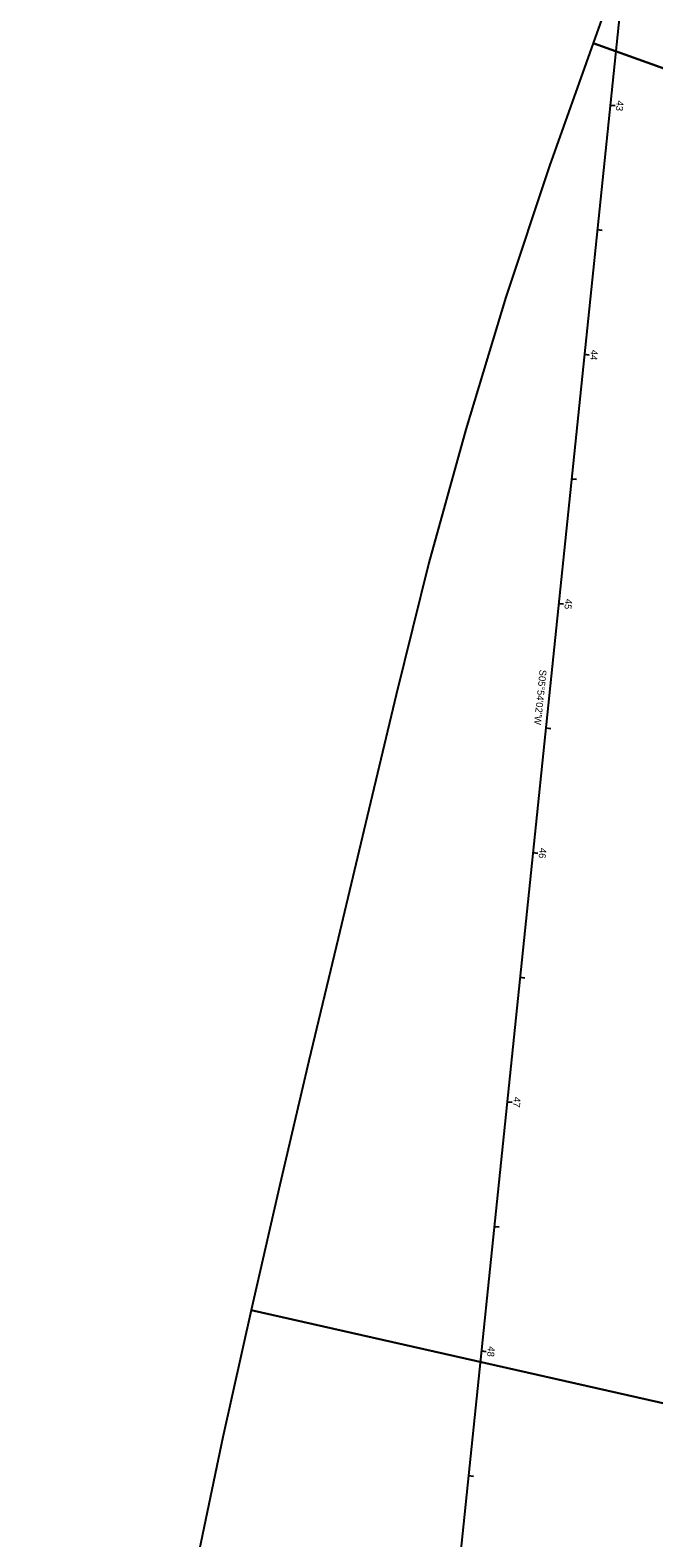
# Model space of a CAD drawing. Extents: x 172043 to 172847, y 249504 to 259737.
# Drawn here: x 172096 to 172345, y 254873 to 255475 of the extents above; entities that cross this region are included whole.
import ezdxf

# ---------------------------------------------------------------- set-up
doc = ezdxf.new("R2010")
doc.units = 0
for name, color, linetype in [('PM_X_Surveyed_Line', 7, 'Continuous'), ('PV_X_Shoulder', 7, 'Continuous'), ('RW_X_CL_100_Distances', 7, 'Continuous')]:
    doc.layers.add(name, color=color, linetype=linetype)

msp = doc.modelspace()

# ---------------------------------------------------------------- linework, layer by layer
at = {"layer": 'PM_X_Surveyed_Line'}
for p, q in [((172428.67, 256423.35), (172177.28, 253990.91)), ((172409.1, 256234.03), (172171.47, 253934.66)), ((172327.53, 255444.75), (172329.52, 255444.55)), ((172327.53, 255444.75), (172329.52, 255444.55)), ((172322.39, 255395.02), (172324.38, 255394.81)), ((172317.25, 255345.28), (172319.24, 255345.08)), ((172317.25, 255345.28), (172319.24, 255345.08)), ((172312.11, 255295.55), (172314.1, 255295.34)), ((172306.97, 255245.81), (172308.96, 255245.61)), ((172306.97, 255245.81), (172308.96, 255245.61)), ((172301.83, 255196.08), (172303.82, 255195.87)), ((172296.69, 255146.34), (172298.68, 255146.14)), ((172296.69, 255146.34), (172298.68, 255146.14)), ((172291.55, 255096.61), (172293.54, 255096.4)), ((172286.41, 255046.87), (172288.4, 255046.67)), ((172286.41, 255046.87), (172288.4, 255046.67)), ((172281.27, 254997.14), (172283.26, 254996.93)), ((172276.13, 254947.4), (172278.12, 254947.2)), ((172270.99, 254897.67), (172272.98, 254897.46))]:
    msp.add_line(p, q, dxfattribs=at)
at = {"layer": 'PV_X_Shoulder'}
for points in [[(172320.75, 255469.43), (172697.36, 255334.65), (172714.21, 255381.73), (172731.06, 255428.8), (172754.44, 255523.13), (172759.7, 255572.85), (172764.97, 255622.58), (172770.23, 255672.3), (172775.5, 255722.02), (172780.76, 255771.74), (172786.03, 255821.46), (172791.29, 255871.19), (172393.52, 255913.31), (172388.25, 255863.59), (172382.99, 255813.87), (172377.72, 255764.14), (172372.46, 255714.42), (172367.19, 255664.7), (172361.93, 255614.98), (172356.66, 255565.26), (172354.45, 255563.58), (172337.6, 255516.51)], [(172184.15, 254963.66), (172574.32, 254875.56), (172585.22, 254922.95), (172596.48, 254970.85), (172608.01, 255019.19), (172619.62, 255067.83), (172631.23, 255116.46), (172642.23, 255160.89), (172654.11, 255204.05), (172667.12, 255246.88), (172681.24, 255289.36), (172697.36, 255334.65), (172320.75, 255469.43), (172303.35, 255420.51), (172285.92, 255368.09), (172269.88, 255315.24), (172255.22, 255261.99), (172242.17, 255209.36), (172230.56, 255160.73), (172218.95, 255112.1), (172207.28, 255063.17), (172195.65, 255013.72)], [(172095.96, 254450.44), (172493.22, 254403.68), (172499.07, 254451.2), (172505.42, 254498.65), (172512.28, 254546.03), (172519.63, 254593.34), (172527.5, 254640.57), (172535.86, 254687.71), (172544.72, 254734.76), (172554.08, 254781.71), (172563.94, 254828.56), (172574.32, 254875.56), (172184.15, 254963.66), (172172.96, 254913.01), (172162.22, 254862), (172152.03, 254810.88), (172142.38, 254759.66), (172133.28, 254708.34), (172124.72, 254656.92), (172116.71, 254605.42), (172109.24, 254553.83), (172102.33, 254502.17)]]:
    msp.add_lwpolyline(points, close=True, dxfattribs=at)
at = {"layer": 'RW_X_CL_100_Distances'}
msp.add_arc((176971.56, 253876.57), 4725.26, 167.78499, 171.05422, dxfattribs=at)

# ---------------------------------------------------------------- texts
at = {"layer": 'PM_X_Surveyed_Line'}
for s, p in [('43', (172330.24, 255446.64)), ('44', (172319.96, 255347.17)), ('45', (172309.68, 255247.73)), ('S05°54\'02"W', (172299.42, 255219.45)), ('46', (172299.41, 255148.31)), ('47', (172289.13, 255048.9)), ('48', (172278.85, 254949.35))]:
    msp.add_text(s, height=2.8, rotation=264.09958, dxfattribs=at).set_placement(p)

doc.saveas('drawing.dxf')
